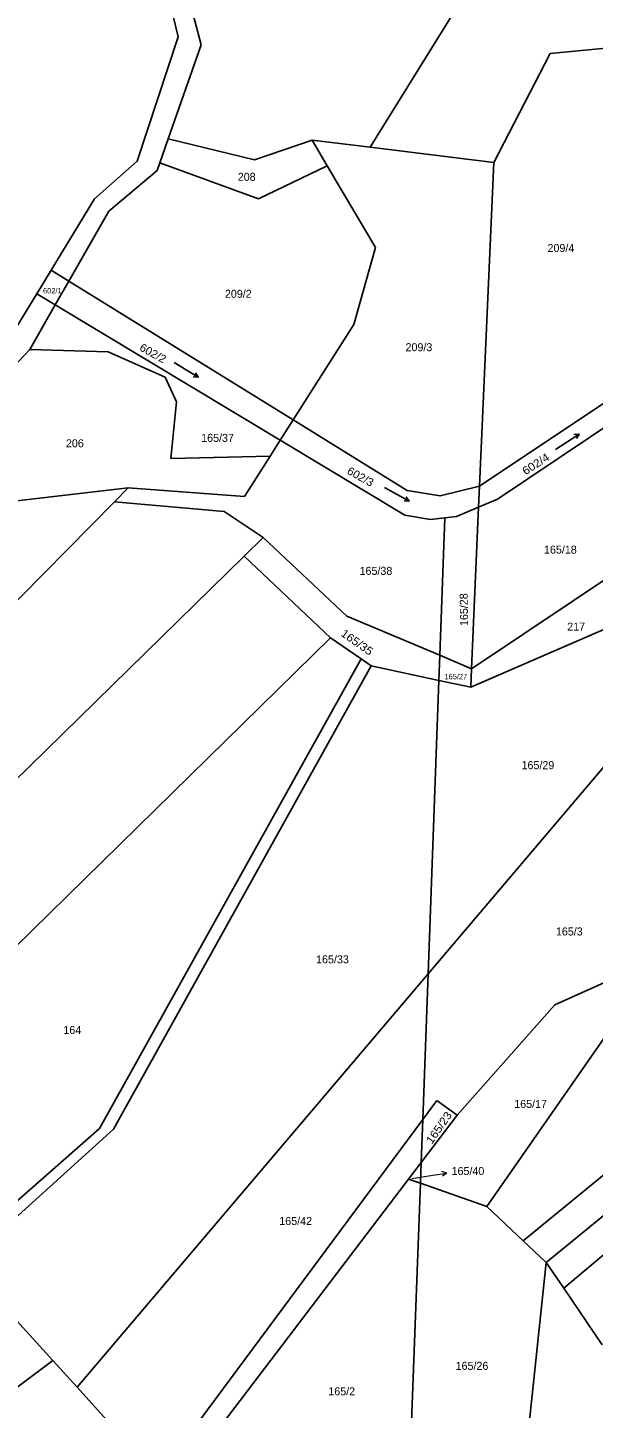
# Model space of a CAD drawing. Extents: x -664548 to -662415, y -1069720 to -1068208.
# Drawn here: x -663233.8 to -663113.6, y -1068738.8 to -1068445.5 of the extents above; entities that cross this region are included whole.
import ezdxf

# ---------------------------------------------------------------- set-up
doc = ezdxf.new("R2010")
doc.units = 0
doc.header["$LTSCALE"] = 0.68
for name, color, linetype, lineweight in [('1', 7, 'Continuous', 25), ('3', 7, 'Continuous', 25), ('7', 7, 'Continuous', 13)]:
    doc.layers.add(name, color=color, linetype=linetype, lineweight=lineweight)
doc.layers.add('2', color=7, linetype='Continuous')

msp = doc.modelspace()

# ---------------------------------------------------------------- linework, layer by layer
at = {"layer": '1'}
for p, q in [((-663131.52, -1068423.16), (-663161.06, -1068470.91)), ((-663206.49, -1068428.19), (-663201.85, -1068447.43)), ((-663196.93, -1068449.13), (-663202.44, -1068428.16)), ((-663201.85, -1068447.43), (-663210.53, -1068473.84)), ((-663203.95, -1068469.1), (-663196.93, -1068449.13)), ((-663122.83, -1068451.01), (-663111.03, -1068449.86)), ((-663134.79, -1068474.13), (-663122.83, -1068451.01)), ((-663205.73, -1068474.18), (-663203.95, -1068469.1)), ((-663185.6, -1068473.6), (-663203.95, -1068469.1)), ((-663185.6, -1068473.6), (-663173.38, -1068469.4)), ((-663161.06, -1068470.91), (-663173.38, -1068469.4)), ((-663170.19, -1068474.81), (-663173.38, -1068469.4)), ((-663134.79, -1068474.13), (-663161.06, -1068470.91)), ((-663210.53, -1068473.84), (-663219.63, -1068481.84)), ((-663216.58, -1068484.48), (-663206.31, -1068475.82)), ((-663206.31, -1068475.82), (-663205.73, -1068474.18)), ((-663184.75, -1068481.83), (-663205.73, -1068474.18)), ((-663184.75, -1068481.83), (-663170.19, -1068474.81)), ((-663159.95, -1068492.18), (-663170.19, -1068474.81)), ((-663137.81, -1068542.89), (-663134.79, -1068474.13)), ((-663219.63, -1068481.84), (-663228.83, -1068497.01)), ((-663225.05, -1068499.35), (-663216.58, -1068484.48)), ((-663164.55, -1068508.53), (-663159.95, -1068492.18)), ((-663228.83, -1068497.01), (-663231.87, -1068502.02)), ((-663225.05, -1068499.35), (-663228.83, -1068497.01)), ((-663227.93, -1068504.39), (-663225.05, -1068499.35)), ((-663177.41, -1068528.83), (-663225.05, -1068499.35)), ((-663231.87, -1068502.02), (-663238.4, -1068512.77)), ((-663227.93, -1068504.39), (-663231.87, -1068502.02)), ((-663233.31, -1068513.83), (-663227.93, -1068504.39)), ((-663180.14, -1068533.13), (-663227.93, -1068504.39)), ((-663177.41, -1068528.83), (-663164.55, -1068508.53)), ((-663269.56, -1068552.21), (-663233.31, -1068513.83)), ((-663233.31, -1068513.83), (-663216.67, -1068514.33)), ((-663216.67, -1068514.33), (-663204.6, -1068519.72)), ((-663204.6, -1068519.72), (-663202.17, -1068524.99)), ((-663137.81, -1068542.89), (-663108.22, -1068523.13)), ((-663202.17, -1068524.99), (-663203.39, -1068537)), ((-663180.14, -1068533.13), (-663177.41, -1068528.83)), ((-663153.21, -1068543.81), (-663177.41, -1068528.83)), ((-663134.02, -1068545.66), (-663108.02, -1068528.23)), ((-663182.29, -1068536.52), (-663180.14, -1068533.13)), ((-663153.72, -1068549.02), (-663180.14, -1068533.13)), ((-663203.39, -1068537), (-663182.29, -1068536.52)), ((-663187.72, -1068545.08), (-663182.29, -1068536.52)), ((-663243.27, -1068546.86), (-663212.46, -1068543.28)), ((-663212.46, -1068543.28), (-663215.35, -1068546.22)), ((-663212.46, -1068543.28), (-663187.72, -1068545.08)), ((-663146.2, -1068544.97), (-663153.21, -1068543.81)), ((-663137.81, -1068542.89), (-663146.2, -1068544.97)), ((-663138.01, -1068547.35), (-663137.81, -1068542.89)), ((-663215.35, -1068546.22), (-663298.92, -1068630.96)), ((-663192.08, -1068548.3), (-663215.35, -1068546.22)), ((-663138.01, -1068547.35), (-663142.73, -1068549.35)), ((-663139.52, -1068581.69), (-663138.01, -1068547.35)), ((-663134.02, -1068545.66), (-663138.01, -1068547.35)), ((-663192.08, -1068548.3), (-663183.76, -1068553.82)), ((-663148.25, -1068549.95), (-663153.72, -1068549.02)), ((-663145.21, -1068549.62), (-663148.25, -1068549.95)), ((-663145.21, -1068549.62), (-663146.28, -1068578.83)), ((-663142.73, -1068549.35), (-663145.21, -1068549.62)), ((-663183.76, -1068553.82), (-663187.78, -1068557.75)), ((-663183.76, -1068553.82), (-663166, -1068570.51)), ((-663187.78, -1068557.75), (-663297.88, -1068665.53)), ((-663169.48, -1068575.09), (-663187.78, -1068557.75)), ((-663072.19, -1068556.23), (-663148.76, -1068646.48)), ((-663139.52, -1068581.69), (-663106.81, -1068559.79)), ((-663166, -1068570.51), (-663146.28, -1068578.83)), ((-663139.69, -1068585.62), (-663106.37, -1068571.11)), ((-663278.79, -1068682.37), (-663169.48, -1068575.09)), ((-663162.95, -1068579.58), (-663169.48, -1068575.09)), ((-663218.52, -1068679.38), (-663162.95, -1068579.58)), ((-663160.82, -1068581.04), (-663162.95, -1068579.58)), ((-663146.28, -1068578.83), (-663146.48, -1068584.15)), ((-663146.28, -1068578.83), (-663139.52, -1068581.69)), ((-663215.58, -1068679.48), (-663160.82, -1068581.04)), ((-663146.48, -1068584.15), (-663160.82, -1068581.04)), ((-663139.52, -1068581.69), (-663139.69, -1068585.62)), ((-663146.48, -1068584.15), (-663148.76, -1068646.48)), ((-663139.69, -1068585.62), (-663146.48, -1068584.15)), ((-663136.26, -1068695.89), (-663099.45, -1068642.94)), ((-663121.8, -1068653.1), (-663099.45, -1068642.94)), ((-663148.76, -1068646.48), (-663223.3, -1068734.34)), ((-663148.76, -1068646.48), (-663149.89, -1068677.42)), ((-663121.8, -1068653.1), (-663142.59, -1068676.54)), ((-663074.17, -1068658.57), (-663128.54, -1068703.2)), ((-663123.64, -1068707.84), (-663068.93, -1068662.81)), ((-663119.95, -1068713.26), (-663064.33, -1068666.53)), ((-663149.89, -1068677.42), (-663146.9, -1068673.38)), ((-663146.9, -1068673.38), (-663142.59, -1068676.54)), ((-663249.36, -1068706.4), (-663218.52, -1068679.38)), ((-663206.12, -1068753.27), (-663149.89, -1068677.42)), ((-663142.59, -1068676.54), (-663150.23, -1068686.58)), ((-663149.89, -1068677.42), (-663150.23, -1068686.58)), ((-663247.14, -1068708.08), (-663215.58, -1068679.48)), ((-663150.23, -1068686.58), (-663152.9, -1068690.09)), ((-663150.23, -1068686.58), (-663150.39, -1068690.96)), ((-663152.9, -1068690.09), (-663199.29, -1068751.1)), ((-663150.39, -1068690.96), (-663152.9, -1068690.09)), ((-663150.39, -1068690.96), (-663152.83, -1068757.51)), ((-663136.26, -1068695.89), (-663150.39, -1068690.96)), ((-663136.26, -1068695.89), (-663128.54, -1068703.2)), ((-663128.54, -1068703.2), (-663123.64, -1068707.84)), ((-663247.14, -1068708.08), (-663228.48, -1068728.63)), ((-663123.64, -1068707.84), (-663129.18, -1068759.71)), ((-663123.64, -1068707.84), (-663119.95, -1068713.26)), ((-663119.95, -1068713.26), (-663111.76, -1068725.32)), ((-663317.89, -1068795.6), (-663228.48, -1068728.63)), ((-663228.48, -1068728.63), (-663223.3, -1068734.34)), ((-663223.3, -1068734.34), (-663206.12, -1068753.27))]:
    msp.add_line(p, q, dxfattribs=at)
at = {"layer": '3'}
for p, q in [((-663197.568, -1068519.731), (-663198.664, -1068519.658)), ((-663116.685, -1068531.814), (-663117.231, -1068532.767)), ((-663152.765, -1068546.05), (-663153.863, -1068546.015))]:
    msp.add_line(p, q, dxfattribs=at)
for points in [[(-663202.711, -1068516.641), (-663197.568, -1068519.731), (-663198.148, -1068518.798)], [(-663121.717, -1068535.082), (-663116.685, -1068531.814), (-663117.778, -1068531.926)], [(-663158.013, -1068543.141), (-663152.765, -1068546.05), (-663153.377, -1068545.138)]]:
    msp.add_lwpolyline(points, dxfattribs=at)
at = {"layer": '7'}
msp.add_line((-663144.756, -1068688.821), (-663145.823, -1068688.483), dxfattribs=at)
msp.add_lwpolyline([(-663152.17, -1068690), (-663147.72, -1068689.29), (-663144.756, -1068688.821), (-663145.667, -1068689.472)], dxfattribs=at)

# ---------------------------------------------------------------- texts
at = {"layer": '2'}
for s, height, p in [('208', 1.7, (-663189.17, -1068478.025)), ('209/4', 1.7, (-663123.38, -1068493.145)), ('602/1', 1.14, (-663230.53, -1068501.944)), ('209/2', 1.7, (-663191.9, -1068502.875)), ('209/3', 1.7, (-663153.54, -1068514.225)), ('165/37', 1.7, (-663196.94, -1068533.485)), ('206', 1.7, (-663225.67, -1068534.635)), ('165/18', 1.7, (-663124.13, -1068557.225)), ('165/38', 1.7, (-663163.3, -1068561.735)), ('217', 1.7, (-663119.2, -1068573.584)), ('165/27', 1.14, (-663145.26, -1068583.914)), ('165/29', 1.7, (-663128.9, -1068603.015)), ('165/3', 1.7, (-663121.6, -1068638.344)), ('165/33', 1.7, (-663172.54, -1068644.265)), ('164', 1.7, (-663226.21, -1068659.275)), ('165/17', 1.7, (-663130.45, -1068674.985)), ('165/40', 1.7, (-663143.76, -1068689.235)), ('165/42', 1.7, (-663180.36, -1068699.854)), ('165/26', 1.7, (-663142.9, -1068730.625)), ('165/2', 1.7, (-663169.94, -1068736.045))]:
    msp.add_text(s, height=height, dxfattribs=at).set_placement(p)
for s, rotation, width, p in [('602/2', 331, 1.05, (-663210.216, -1068513.941)), ('602/4', 33, 1.1, (-663128.048, -1068540.606)), ('602/3', 331, 1.05, (-663166.126, -1068540.171)), ('165/35', 325, 1.1, (-663167.453, -1068574.558)), ('165/23', 55, 1.1, (-663147.941, -1068682.803))]:
    msp.add_text(s, height=1.7, rotation=rotation, dxfattribs=dict(at, width=width)).set_placement(p)
msp.add_text('165/28', height=1.7, rotation=91, dxfattribs=at).set_placement((-663140.235, -1068572.592))

doc.saveas('drawing.dxf')
